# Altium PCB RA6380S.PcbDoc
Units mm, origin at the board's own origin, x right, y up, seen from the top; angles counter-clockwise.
Board outline 105 x 77 mm, 2 copper layers (Top Layer, Bottom Layer); 47 components, 24 nets, 110 pads, 0 vias.
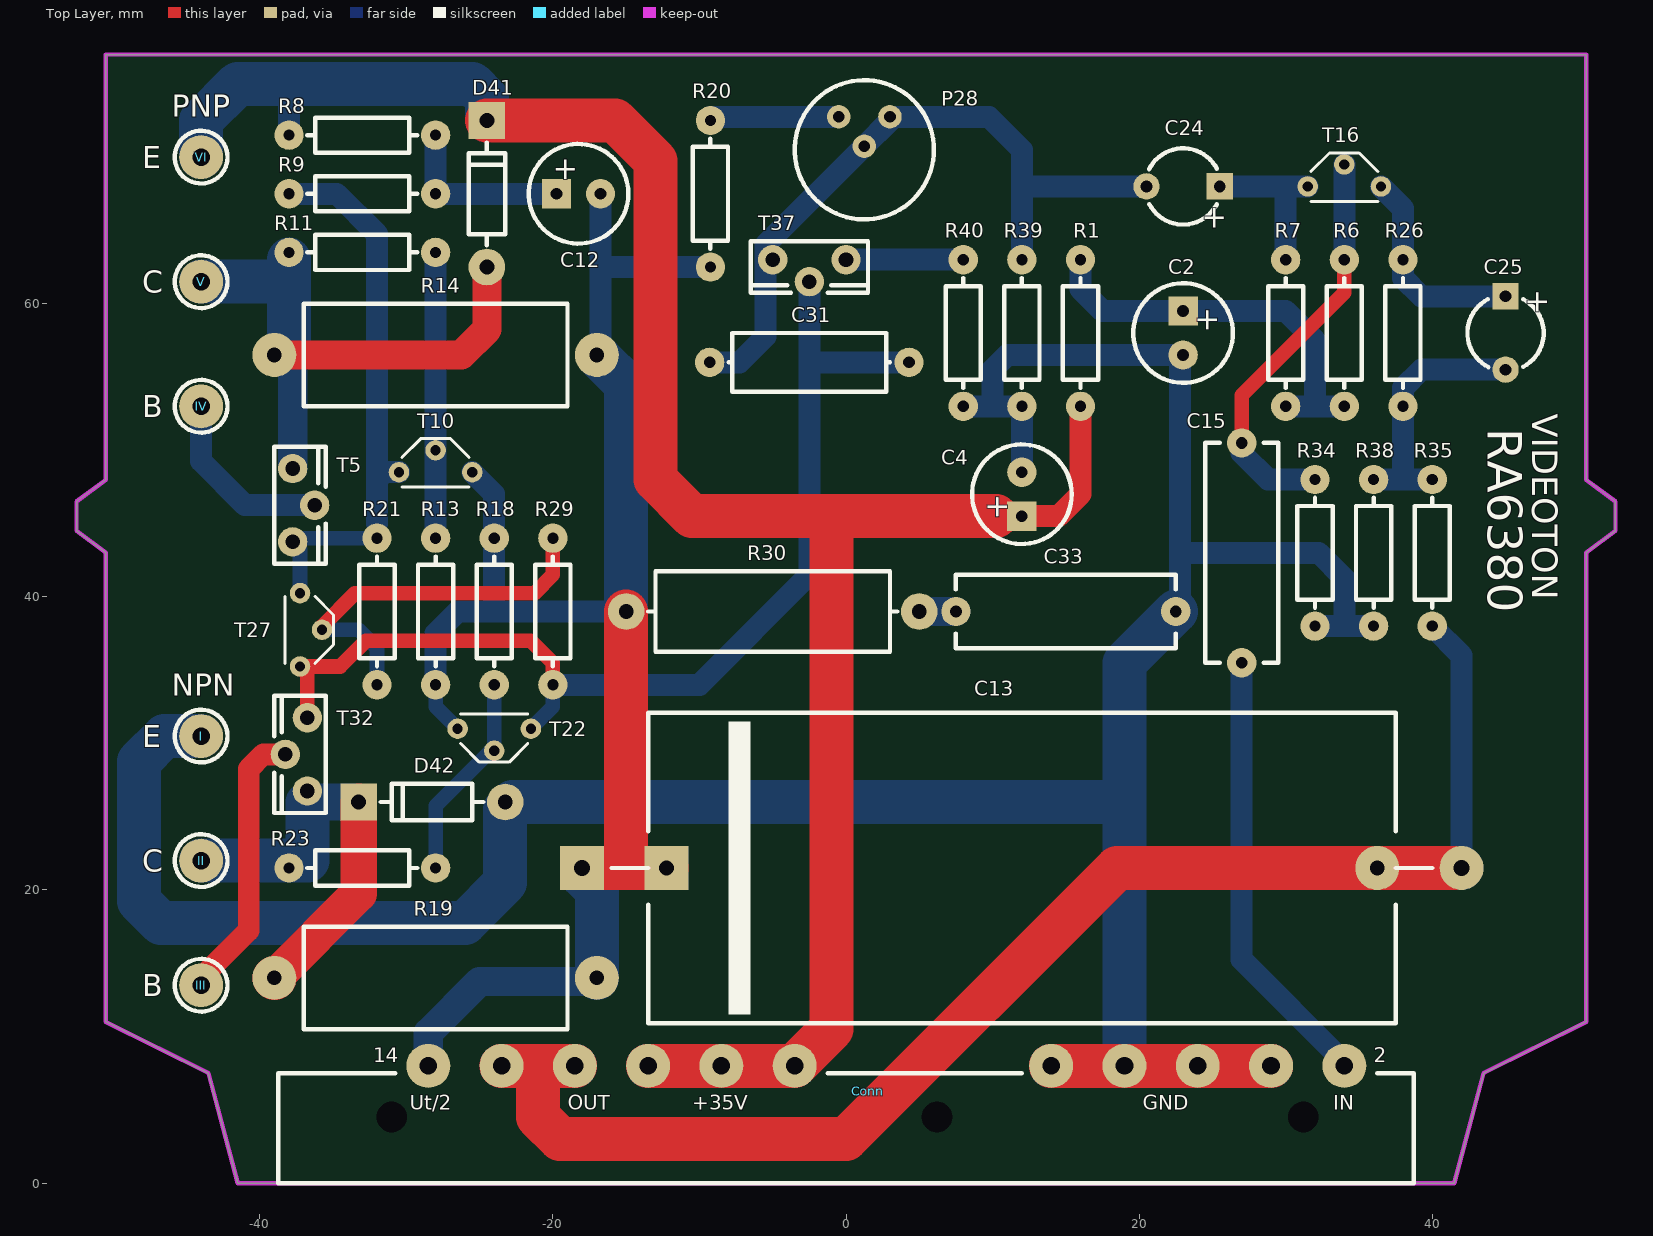
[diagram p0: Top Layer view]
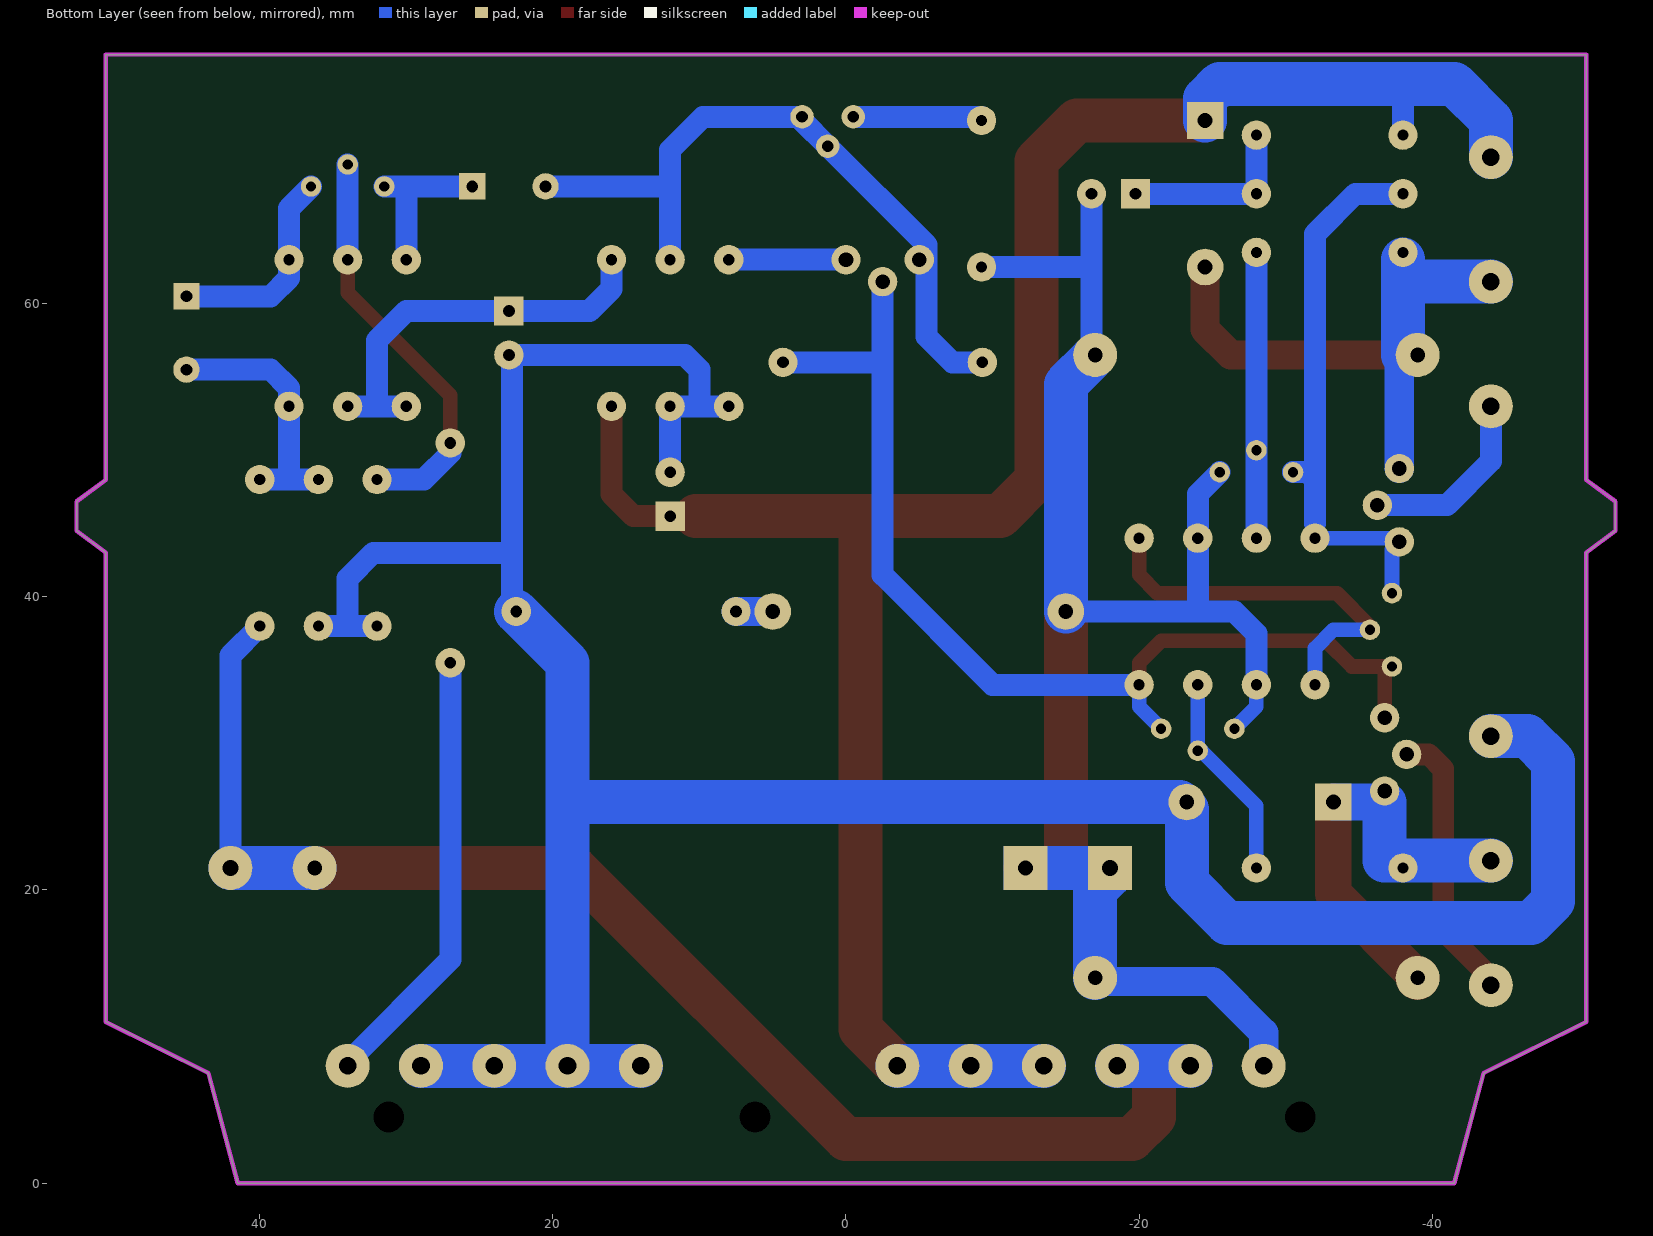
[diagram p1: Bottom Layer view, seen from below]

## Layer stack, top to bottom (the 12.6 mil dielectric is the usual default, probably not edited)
Top Solder: solder mask 0.0102, Solder Resist, Dk 3.5
Top Layer: signal copper 0.0356
Dielectric 1: dielectric 0.32, FR-4, Dk 4.8
Bottom Layer: signal copper 0.0356
Bottom Solder: solder mask 0.0102, Solder Resist, Dk 3.5

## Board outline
-52.5,44.5 -50.5,43 -50.5,11 -43.5,7.5 -41.5,0 41.5,0 43.5,7.5 50.5,11 50.5,43 52.5,44.5 52.5,46.5 50.5,48 50.5,77 -50.5,77 -50.5,48 -52.5,46.5

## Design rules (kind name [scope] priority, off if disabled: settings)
Clearance [All] p1: gap=0.254
PolygonConnect [All] p1: connectstyle=Relief reliefconductorwidth=0.254 reliefentries=4 polygonreliefangle="90 Angle" airgapwidth=0.254
RoutingVias [All] p1: holewidth=0.711 width=1.27 viastyle="Through Hole" minholewidth=0.711 minwidth=1.27 maxholewidth=0.711 maxwidth=1.27
SolderMaskExpansion [All] p1: expansion=0.102
Width [All] p1: maxlimit=4 minlimit=1 preferedwidth=1
30 further rules are at their usual default settings.

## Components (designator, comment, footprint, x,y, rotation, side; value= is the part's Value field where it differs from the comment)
C2 "100u" 038RSU 23,58 r270 top
C4 "47u" 038RSU 12,47 r90 top
C12 "47u" 038RSU -18.25,67.5 r0 top
C13 "2200uF" "2200uF 40V axial" 12,21.5 r0 top locked
C15 "470n" "C2334 400V" 27,43 r90 top
C24 "22u" MAL203831229E3 23,68 r180 top
C25 "22u" MAL203831229E3 45,58 r270 top
C31 "330p" C2441 -2.5,56 r0 top
C33 "220n" "C2334 400V" 15,39 r180 top
Conn "Videoton Cleopatra connector" "Videoton Cleopatra connector" 0,8 r0 top locked
D41 "4007" DO-41 -24.5,67.5 r270 top
D42 "4007" DO-41 -28.25,26 r0 top
I "1pin" "1pin 1.4x3" -44,30.5 r90 top locked
II "1pin" "1pin 1.4x3" -44,22 r0 top locked
III "1pin" "1pin 1.4x3" -44,13.5 r0 top locked
IV "1pin" "1pin 1.4x3" -44,53 r0 top locked
P28 "22k" TP095 1.25,70.5 r0 top
R1 "27k" MF0207 16,58 r90 top
R6 "330k" MF0207 34,58 r270 top
R7 "10k" MF0207 30,58 r270 top
R8 "680R" MF0207 -33,71.5 r180 top
R9 "1k8" MF0207 -33,67.5 r0 top
R11 "100R" MF0207 -33,63.5 r0 top
R13 "220R" MF0207 -28,39 r90 top
R14 "0R16 5W" KNP5WS -28,56.5 r0 top locked
R18 "220R" MF0207 -24,39 r90 top
R19 "0R16 5W" KNP5WS -28,14 r180 top locked
R20 "22k" MF0207 -9.25,67.5 r270 top
R21 "150R" MF0207 -32,39 r90 top
R23 "100R" MF0207 -33,21.5 r0 top
R26 "4k7" MF0207 38,58 r90 top
R29 "220R" MF0207 -20,39 r90 top
R30 "4R7" MOR03 -5,39 r0 top
R34 "150k" MF0207 32,43 r90 top
R35 "8k2" MF0207 40,43 r90 top
R38 "390R" MF0207 36,43 r90 top
R39 "2k7" MF0207 12,58 r90 top
R40 "68R" MF0207 8,58 r90 top
T5 "BD139" BD139 -37.25,46.25 r270 top
T10 "BC182B" BC557 -28,48.5 r180 top
T16 "BC182B" BC547 34,68 r180 top
T22 "BC213B" BC557 -24,31 r0 top
T27 "BC182B" BC557 -37.25,37.75 r90 top
T32 "BD140" BD139 -37.25,29.25 r90 top
T37 "BD139" BD139 -2.5,62.5 r180 top
V "1pin" "1pin 1.4x3" -44,61.5 r90 top locked
VI "1pin" "1pin 1.4x3" -44,70 r0 top locked

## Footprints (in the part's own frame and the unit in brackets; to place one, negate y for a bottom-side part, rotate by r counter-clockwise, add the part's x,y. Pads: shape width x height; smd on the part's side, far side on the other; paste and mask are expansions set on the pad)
"1pin 1.4x3" [mm]
  round 3 hole 1.2: 1(0,0)
  silkscreen extent -1.8,-1.8 1.8,1.8
038RSU [mm] "6.8x12mm 2mm wishay cap pol"
  rect 2x2 hole 0.8: 1(-1.5,0)
  round 2 hole 0.8: 2(1.5,0)
  silkscreen extent -3.4,-3.4 3.4,3.4, body extent -3.4,-3.4 3.4,3.4, height 12
"2200uF 40V axial" [mm]
  rect 3x3 hole 1.1: 1(-30,0)
  rect 3x3 hole 1: 1(-24.25,0)
  round 3 hole 1: 2(24.25,0)
  round 3 hole 1.1: 2(30,0)
  silkscreen extent -28,-10.6 28,10.6, body extent -25.5,-10.5 25.5,10.5, height 20.99
BC547 [mm]
  round 1.4 hole 0.7: B(0,-1.5) C(2.5,0) E(-2.5,0)
  silkscreen extent -2.29,-2.29 2.29,1.02, body extent -2.3,-2.3 2.3,1, height 9.3
BC557 [mm]
  round 1.4 hole 0.7: B(0,-1.5) C(2.5,0) E(-2.5,0)
  silkscreen extent -2.29,-2.29 2.29,1.02, body extent -2.3,-2.3 2.3,1, height 9.3
BD139 [mm]
  round 2 hole 1: B(2.5,-0.5) C(0,1) E(-2.5,-0.5)
  silkscreen extent -4,-1.75 4,1.75, body extent -4,-1.75 4,1.75, height 15
"C2334 400V" [mm]
  round 2 hole 0.8: 1(-7.5,0) 2(7.5,0)
  silkscreen extent -7.5,-2.5 7.5,2.5, body extent -7.5,-2.5 7.5,2.5, height 7
C2441 [mm]
  round 2 hole 0.8: 1(-6.8,0) 2(6.8,0)
  silkscreen extent -5.5,-2 5.5,2, body extent -5.25,-2 5.35,2, height 4.5
DO-41 [mm]
  round 2.5 hole 1.016: A(5,0)
  rect 2.5x2.5 hole 1.016: K(-5,0)
  silkscreen extent -3.5,-1.25 3.5,1.25, body extent -2.6,-1.3 2.6,1.3, height 3.3
KNP5WS [mm]
  round 3 hole 1: 1(-11,0) 2(11,0)
  silkscreen extent -9,-3.5 9,3.5, body extent -9,-3.5 9,3.5, height 7.5
MAL203831229E3 [mm]
  rect 1.8x1.8 hole 0.8: 1(-2.5,0)
  round 1.8 hole 0.8: 2(2.5,0)
  silkscreen extent -2.31,-2.6 2.33,2.6, body extent -2.5,-2.5 2.5,2.5, height 12
MF0207 [mm]
  round 2 hole 0.762: 1(-5,0) 2(5,0)
  silkscreen extent -3.75,-1.2 3.75,1.2, body extent -3.4,-1.27 3.4,1.27, height 2.77
MOR03 [mm] "3W resistor"
  round 2.5 hole 1: 1(-10,0) 2(10,0)
  silkscreen extent -8.5,-2.75 8.5,2.75, body extent -8,-2.75 8,2.75, height 5.75
TP095 [mm]
  round 1.6 hole 0.8: 1(-1.75,2.25) 2(1.75,2.25) W(0,0.25)
  silkscreen extent -4.75,-4.75 4.75,4.75, body extent -4.75,-4.75 4.75,4.75, height 6.4
"Videoton Cleopatra connector" [mm]
  round 3 hole 1.2: 2(34,0) 3(29,0) 4(24,0) 5(19,0) 6(14,0) 9(-3.5,0) 10(-8.5,0) 11(-13.5,0) 12(-18.5,0) 13(-23.5,0) 14(-28.5,0)
  round 0 hole 2.1: 16(31.2,-3.5) 17(6.2,-3.5) 18(-31,-3.5)
  silkscreen extent -38.75,-8 38.75,-0.5, body extent -38.75,-8 38.75,-0.5, height 8

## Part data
C2 C4 C12 C13 C24 C25: library part "CAP POL"
C15 C31 C33: library part CAP
D41 D42: library part Dioda
P28: library part "RES POT2"
R1 R6 R7 R8 R9 R11 R13 R14 R18 R19 R20 R21 R23 R26 R29 R30 R34 R35 R38 R39 R40: library part RES_THT
T5 T10 T16 T27 T37: library part NPN
T22 T32: library part PNP

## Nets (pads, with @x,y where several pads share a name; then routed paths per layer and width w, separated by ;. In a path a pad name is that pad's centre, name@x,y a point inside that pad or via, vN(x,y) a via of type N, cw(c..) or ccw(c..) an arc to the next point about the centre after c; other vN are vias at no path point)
2: C15.1 Conn.2 | length 30.4
  Bottom Layer w1.5: C15.1 27,15.25 34,8.25 Conn.2
3: C2.2 C4.2 C33.1 Conn.3 Conn.4 Conn.5 Conn.6 D42.A I.1 R34.1 R38.1 R39.1 R40.1 | length 212.2
  Top Layer w3: Conn.6 Conn.5 Conn.4 Conn.3
  Bottom Layer w1.5: R40.1 10,53 ; C4.2 R39.1 10,53 ; C33.1@22.8,39.3 22.8,56.3 C2.2 11,56.5 10,55.5 10,53 ; 22.8,43 32.25,43 34,41.25 34,38 ; R34.1 34,38 ; R38.1 34,38
  Bottom Layer w2: 18.5,26 19,25.5
  Bottom Layer w3: I.1 -46.5,30.5 -48.25,28.75 -48.25,19.25 -46.75,17.75 -26,17.75 -23.25,20.5 -23.25,25.5 -22.75,26 18.5,26 ; Conn.6 Conn.5 ; C33.1 19,35.5 19,25.5 Conn.5 ; Conn.3 Conn.4 Conn.5
9: C4.1 Conn.9 Conn.10 Conn.11 D41.K R1.1 R8.2 VI.1 | length 156
  Top Layer w1.5: C4.1 14.5,45.5 16,47 R1.1
  Top Layer w3: D41.K -15.75,72.5 -13,69.75 -13,48 -10.5,45.5 10.25,45.5 ; Conn.11 Conn.10 Conn.9 -1,10.5 -1,45.5
  Bottom Layer w1.5: R8.2 -38,75
  Bottom Layer w3: VI.1 -44,72.5 -41.5,75 -38,75 ; -37.75,75 -25.5,75 -24.5,74 D41.K ; Conn.11 Conn.10 Conn.9
12: C13.2 Conn.12 Conn.13 R35.1 | length 107.4
  Top Layer w3: Conn.13 -21,8 ; Conn.12 -21,8 ; C13.2@41.5,21.5 18.5,21.5 0,3 -19.5,3 -21,4.5 -21,8
  Bottom Layer w1.5: R35.1 42,36 C13.2@42,21.5
  Bottom Layer w3: Conn.13 Conn.12 ; C13.2@36.25,21.5 C13.2@42,21.5
14: C12.2 C13.1 Conn.14 R13.1 R14.2 R18.2 R19.1 R20.2 R30.1 T10.E T22.E | length 112.8
  Top Layer w3: C13.1@-18,21.5 -15,21.5 ; R30.1 -15,21.5 ; C13.1@-12.25,21.5 -15,21.5
  Bottom Layer w1: R13.1 -28,32.5 T22.E
  Bottom Layer w1.5: R13.1 -28,37.5 -26.5,39 -24,39 ; T10.E -24,47 -24,39 ; R14.2@-16.75,56.5 -16.75,62.5 ; C12.2 -16.75,62.5 ; R30.1 -24,39 ; R20.2@-9.75,62.5 -16.75,62.5
  Bottom Layer w2: Conn.14 -28.5,10.25 -25,13.75 -17.25,13.75 R19.1
  Bottom Layer w3: C13.1@-18,21 -17,20 R19.1 ; R14.2@-16.75,56.25 -15,54.5 R30.1
NetC2_1: C2.1 R1.2 R6.2 R7.2 | length 27.9
  Bottom Layer w1.5: R1.2 16,61 17.5,59.5 C2.1 30,59.5 32,57.5 32,53 ; R7.2 R6.2
NetC12_1: C12.1 R8.1 R9.2 | length 12
  Bottom Layer w1.5: R8.1 R9.2 C12.1@-20,67.5
NetC15_2: C15.2 R6.1 R34.2 T16.B | length 28.1
  Top Layer w1: C15.2 27,53.75 34,60.75 R6.1 R6.1@33.75,63
  Bottom Layer w1: R6.1@34,62.75 R6.1
  Bottom Layer w1.5: C15.2@27,49.8 28.8,48 R34.2 ; R6.1 T16.B
NetC24_1: C24.1 R7.1 T16.C | length 11
  Bottom Layer w1.5: C24.1 30,68 ; R7.1 30,68 ; T16.C 30,68
NetC24_2: C24.2 C31.1 P28.2 P28.W R39.2 T37.B | length 51.3
  Bottom Layer w1.5: C31.1@-9,56 -7.25,56 -5.5,57.75 -5.5,64 P28.W ; P28.2 3,72.5 P28.W ; R39.2 12,68 ; C24.2 12,68 ; P28.W 3.25,72.75 9.75,72.75 12,70.5 12,68
NetC25_1: C25.1 R26.2 T16.E | length 13.4
  Bottom Layer w1.5: T16.E 38,66.5 R26.2 38,61.75 39.25,60.5 44,60.5
NetC25_2: C25.2 R26.1 R35.2 R38.2 | length 17.5
  Bottom Layer w1.5: R38.2 38,48 ; R35.2 38,48 ; C25.2@44.75,55.5 39.25,55.5 38,54.25 R26.1 38,48
NetC31_2: C31.2 R29.1 T22.C T27.E T32.B T37.C | length 73.8
  Top Layer w1: T32.B -36.75,34.75 T27.E -34.5,35.25 -32.75,37 -21.5,37 -20,35.5 R29.1
  Bottom Layer w1: T22.C -20,32.5 R29.1
  Bottom Layer w1.5: R29.1 -10,34 -2.5,41.5 T37.C@-2.5,61 ; -2.5,56 C31.2@3.8,56
NetC33_2: C33.2 R30.2 | length 2.5
  Bottom Layer w2: R30.2 C33.2
NetD41_A: D41.A R11.1 R14.1 T5.E V.1 | length 40.3
  Top Layer w2: R14.1 -26.25,56.5 -24.5,58.25 -24.5,61 D41.A
  Bottom Layer w2: R14.1@-38,56.5 R14.1@-37.75,56.25 ; T5.E R14.1@-37.75,56.75
  Bottom Layer w3: V.1 -38,61.5 ; R14.1@-38,56.5 -38,61 R11.1@-38,63
NetD42_K: D42.K II.1 R19.2 R23.1 T32.E | length 29.5
  Top Layer w2.5: R19.2 -33.25,19.75 D42.K
  Bottom Layer w2: D42.K@-33.5,26.25 D42.K
  Bottom Layer w2.5: T32.E@-37,26 D42.K
  Bottom Layer w3: II.1 -38.25,22 -36.75,22 -36.75,25.75
NetIII_1: III.1 T32.C | length 19.5
  Top Layer w1: III.1 -44,14 III.1
  Top Layer w1.5: III.1@-44,14 -40.75,17.25 -40.75,28.25 -39.75,29.25 T32.C
NetIV_1: IV.1 T5.C | length 12.7
  Bottom Layer w1.5: IV.1 -44,49.25 -41,46.25 T5.C
NetP28_1: P28.1 R20.1 | length 8.8
  Bottom Layer w1.5: R20.1@-9.25,72.75 P28.1
NetR9_1: R9.1 R21.2 T5.B T10.C T27.C | length 37.4
  Bottom Layer w1: T5.B -37.5,44 R21.2 ; T27.C T5.B@-37.25,43.25
  Bottom Layer w1.5: R9.1 -34.75,67.5 -32,64.75 -32,48 ; R21.2@-32,45 -32,48 ; T10.C -31.5,48.5 -32,48
NetR11_2: R11.2 R13.2 T10.B | length 19.5
  Bottom Layer w1.5: R13.2 -28,48.5 R11.2
NetR18_1: R18.1 R23.2 T22.B | length 14.3
  Bottom Layer w1: R23.2 -28,25.75 -24.25,29.5 T22.B R18.1
NetR21_1: R21.1 R29.2 T27.B | length 26.7
  Top Layer w1: T27.B@-35.75,37.754 -35.75,38 -33.5,40.25 -21.25,40.25 -20,41.5 R29.2
  Bottom Layer w1: T27.B -33.25,37.75 -32,36.5 R21.1
NetR40_2: R40.2 T37.E | length 8
  Bottom Layer w1.5: T37.E R40.2
pads on no net: Conn.16 Conn.17 Conn.18

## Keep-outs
Keep-Out Layer:
  lines w0.3: -52.5,44.5 -50.5,43 -50.5,11 -43.5,7.5 -41.5,0 41.5,0 43.5,7.5 50.5,11 50.5,43 52.5,44.5 52.5,46.5 50.5,48 50.5,77 -50.5,77 -50.5,71.5 -50.5,48 -52.5,46.5 -52.5,44.5

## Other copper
Bottom Layer:
  rectangle net 14: -19.5,20 -10.75,23

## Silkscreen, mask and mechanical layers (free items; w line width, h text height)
Top Overlay:
  text "PNP" at -46,72.75 h1.5
  text "E" at -48,69.25 h1.5
  text "C" at -48,60.75 h1.5
  text "VIDEOTON" at 46.25,52.5 h3 r270
  text "B" at -48,52.25 h1.5
  text "RA6380" at 43,51.5 h4 r270
  text "NPN" at -46,33.25 h1.5
  text "E" at -48,29.75 h1.5
  text "C" at -48,21.25 h1.5
  text "B" at -48,12.75 h1.5
  text "14" at -32.25,8.25 h1
  text "2" at 36,8.25 h1
  text "Ut/2" at -29.75,5 h1
  text "OUT" at -19,5 h1
  text "+35V" at -10.5,5 h1
  text "GND" at 20.25,5 h1
  text "IN" at 33.25,5 h1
